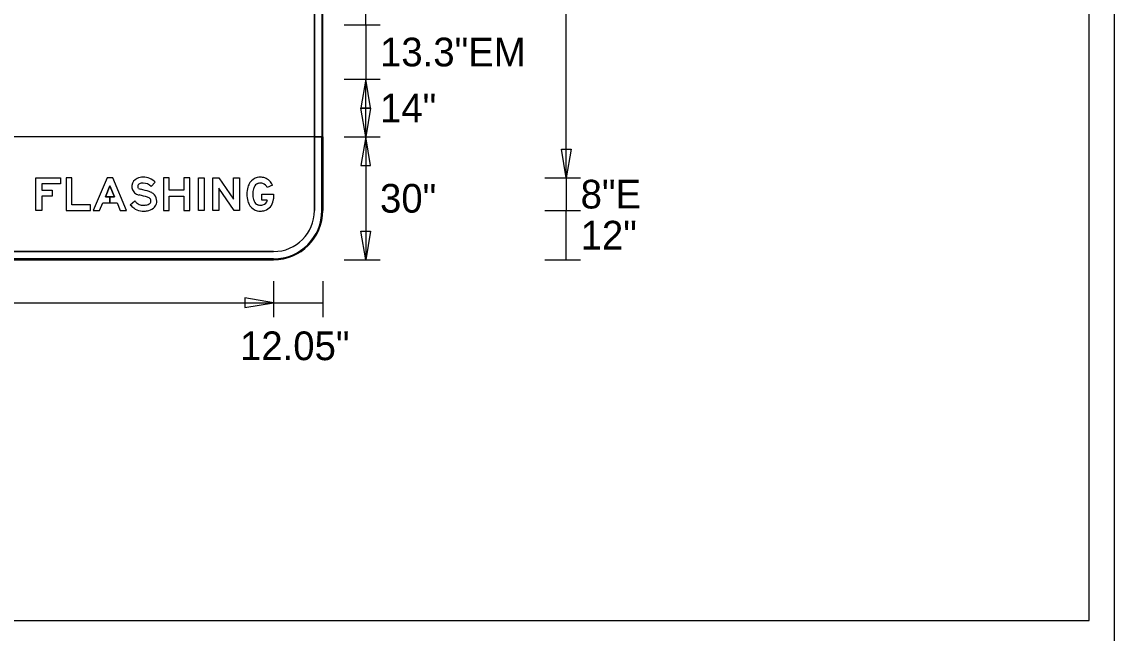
# Model space of a CAD drawing. Extents: x 17890484 to 17890754, y 17897495 to 17897992.
# Drawn here: x 17890542.41 to 17890564.64, y 17897525.26 to 17897537.69 of the extents above; entities that cross this region are included whole.
import ezdxf

# ---------------------------------------------------------------- set-up
doc = ezdxf.new("R2010")
doc.units = 0
for name, color, linetype in [('GSBWFill', 7, 'Continuous'), ('GSColorFill', 7, 'Continuous'), ('GSDims', 7, 'Continuous'), ('GSOutline', 7, 'Continuous'), ('SheetLinesMisc2_dp', 7, 'Continuous')]:
    doc.layers.add(name, color=color, linetype=linetype)

msp = doc.modelspace()

# ---------------------------------------------------------------- linework, layer by layer
at = {"layer": 'GSBWFill'}
for p, q in [((17890548.365, 17897541.854), (17890548.365, 17897533.854)), ((17890548.531, 17897533.854), (17890548.531, 17897541.854)), ((17890548.531, 17897535.354), (17890528.531, 17897535.354)), ((17890548.365, 17897535.187), (17890548.365, 17897535.354)), ((17890548.365, 17897535.354), (17890548.531, 17897535.354)), ((17890548.531, 17897535.354), (17890548.531, 17897533.854)), ((17890548.531, 17897533.854), (17890548.531, 17897535.354)), ((17890548.365, 17897533.854), (17890548.365, 17897535.187)), ((17890529.531, 17897533.021), (17890547.531, 17897533.021)), ((17890547.531, 17897532.854), (17890529.531, 17897532.854)), ((17890529.531, 17897532.854), (17890547.531, 17897532.854)), ((17890547.531, 17897533.021), (17890529.533, 17897533.021)), ((17890529.533, 17897532.854), (17890547.531, 17897532.854))]:
    msp.add_line(p, q, dxfattribs=at)
for points in [[(17890542.815, 17897534.147), (17890542.815, 17897533.854), (17890542.695, 17897533.854), (17890542.695, 17897534.521), (17890543.195, 17897534.521), (17890543.195, 17897534.401), (17890542.815, 17897534.401), (17890542.815, 17897534.267), (17890543.025, 17897534.267), (17890543.025, 17897534.147)], [(17890543.808, 17897533.854), (17890543.808, 17897533.971), (17890543.428, 17897533.971), (17890543.428, 17897534.521), (17890543.308, 17897534.521), (17890543.308, 17897533.854)], [(17890544.295, 17897534.131), (17890544.201, 17897534.131), (17890544.201, 17897534.011), (17890544.345, 17897534.011), (17890544.411, 17897533.854), (17890544.541, 17897533.854), (17890544.261, 17897534.521), (17890544.141, 17897534.521), (17890543.861, 17897533.854), (17890543.991, 17897533.854), (17890544.057, 17897534.011), (17890544.201, 17897534.011), (17890544.201, 17897534.131), (17890544.108, 17897534.131), (17890544.201, 17897534.354)], [(17890545.708, 17897534.267), (17890545.408, 17897534.267), (17890545.408, 17897534.521), (17890545.288, 17897534.521), (17890545.288, 17897533.854), (17890545.408, 17897533.854), (17890545.408, 17897534.147), (17890545.708, 17897534.147), (17890545.708, 17897533.854), (17890545.828, 17897533.854), (17890545.828, 17897534.521), (17890545.708, 17897534.521)], [(17890546.001, 17897533.854), (17890546.001, 17897534.521), (17890546.121, 17897534.521), (17890546.121, 17897533.854)], [(17890546.835, 17897534.521), (17890546.835, 17897533.854), (17890546.731, 17897533.854), (17890546.415, 17897534.311), (17890546.415, 17897533.854), (17890546.295, 17897533.854), (17890546.295, 17897534.521), (17890546.415, 17897534.521), (17890546.715, 17897534.089), (17890546.715, 17897534.521)]]:
    msp.add_lwpolyline(points, close=True, dxfattribs=at)
for points in [[(17890545.124, 17897534.429), (17890545.038, 17897534.345)], [(17890547.51, 17897534.37), (17890547.399, 17897534.325)], [(17890547.404, 17897534.067), (17890547.294, 17897534.067), (17890547.294, 17897534.187), (17890547.528, 17897534.187), (17890547.528, 17897534.091)], [(17890544.615, 17897533.972), (17890544.705, 17897534.051)]]:
    msp.add_lwpolyline(points, dxfattribs=at)
for centre, radius, start, end in [((17890544.837, 17897534.345), 0.191, 174.1421, 201.2247), ((17890544.821, 17897534.346), 0.174, 113.3248, 174.1421), ((17890544.878, 17897534.214), 0.318, 90, 113.3248), ((17890544.821, 17897534.346), 0.0543, 113.3248, 174.1421), ((17890544.878, 17897534.214), 0.198, 90, 113.3248), ((17890544.878, 17897534.187), 0.345, 44.4342, 90), ((17890544.878, 17897534.187), 0.225, 44.4342, 90), ((17890547.342, 17897534.232), 0.348, 146.7742, 163.4624), ((17890547.252, 17897534.291), 0.24, 103.1315, 146.7742), ((17890547.342, 17897534.232), 0.228, 146.7742, 163.4624), ((17890547.252, 17897534.291), 0.12, 103.1315, 146.7742), ((17890547.263, 17897534.243), 0.289, 90, 103.1315), ((17890547.263, 17897534.243), 0.169, 90, 103.1315), ((17890547.263, 17897534.252), 0.28, 71.2015, 90), ((17890547.263, 17897534.252), 0.16, 71.2015, 90), ((17890547.27, 17897534.272), 0.139, 22.0367, 71.2015), ((17890547.27, 17897534.272), 0.259, 22.0367, 71.2015), ((17890544.798, 17897534.33), 0.149, 201.2247, 240.1812), ((17890544.867, 17897534.45), 0.288, 240.1812, 256.1067), ((17890544.837, 17897534.345), 0.0706, 174.1421, 201.2247), ((17890544.798, 17897534.33), 0.029, 201.2247, 240.1812), ((17890544.867, 17897534.45), 0.168, 240.1812, 256.1067), ((17890544.05, 17897531.146), 3.116, 72.8961, 76.1067), ((17890544.05, 17897531.146), 3.236, 72.8961, 76.1067), ((17890544.907, 17897533.933), 0.32, 63.0108, 72.8961), ((17890544.972, 17897534.059), 0.178, 39.5561, 63.0108), ((17890544.955, 17897534.046), 0.199, 0, 39.5561), ((17890547.493, 17897534.187), 0.505, 163.4624, 180), ((17890547.493, 17897534.187), 0.505, 180, 196.5376), ((17890547.493, 17897534.187), 0.385, 163.4624, 180), ((17890547.493, 17897534.187), 0.385, 180, 196.5376), ((17890544.966, 17897534.276), 0.464, 220.8202, 232.6492), ((17890544.966, 17897534.276), 0.344, 220.8202, 232.6492), ((17890544.869, 17897534.149), 0.185, 232.6492, 260.7349), ((17890544.89, 17897534.273), 0.31, 260.7349, 270), ((17890544.89, 17897534.208), 0.245, 270, 281.6446), ((17890544.899, 17897534.159), 0.196, 281.6446, 306.0677), ((17890544.907, 17897533.933), 0.2, 63.0108, 72.8961), ((17890544.972, 17897534.059), 0.0579, 39.5561, 63.0108), ((17890544.988, 17897534.037), 0.045, 306.0677, 343.4972), ((17890544.955, 17897534.046), 0.0794, 0, 39.5561), ((17890544.96, 17897534.046), 0.0746, 343.4972, 0), ((17890544.988, 17897534.037), 0.165, 306.0677, 343.4972), ((17890544.96, 17897534.046), 0.195, 343.4972, 0), ((17890547.342, 17897534.143), 0.348, 196.5376, 213.2258), ((17890547.252, 17897534.084), 0.24, 213.2258, 256.8685), ((17890547.342, 17897534.143), 0.228, 196.5376, 213.2258), ((17890547.252, 17897534.084), 0.12, 213.2258, 256.8685), ((17890547.263, 17897534.132), 0.169, 256.8685, 270), ((17890547.263, 17897534.122), 0.16, 270, 288.7985), ((17890547.27, 17897534.102), 0.139, 288.7985, 345.418), ((17890547.27, 17897534.102), 0.259, 288.7985, 349.6765), ((17890547.33, 17897534.091), 0.198, 349.6765, 0), ((17890544.869, 17897534.149), 0.305, 232.6492, 260.7349), ((17890544.89, 17897534.273), 0.43, 260.7349, 270), ((17890544.89, 17897534.208), 0.365, 270, 281.6446), ((17890544.899, 17897534.159), 0.316, 281.6446, 306.0677), ((17890547.263, 17897534.132), 0.289, 256.8685, 270), ((17890547.263, 17897534.122), 0.28, 270, 288.7985), ((17890547.531, 17897533.854), 1, 270, 0), ((17890547.531, 17897533.854), 0.833, 270, 0), ((17890547.531, 17897533.854), 1, 270, 0), ((17890547.531, 17897533.854), 0.833, 270, 0), ((17890547.531, 17897533.854), 1, 270, 0)]:
    msp.add_arc(centre, radius, start, end, dxfattribs=at)
at = {"layer": 'GSColorFill'}
for p, q in [((17890548.365, 17897541.854), (17890548.365, 17897533.854)), ((17890548.515, 17897541.854), (17890548.515, 17897533.854)), ((17890548.531, 17897533.854), (17890548.531, 17897541.854)), ((17890548.531, 17897533.854), (17890548.531, 17897541.854)), ((17890548.531, 17897533.854), (17890548.531, 17897541.854)), ((17890548.531, 17897535.354), (17890528.531, 17897535.354)), ((17890548.365, 17897535.187), (17890548.365, 17897535.354)), ((17890548.365, 17897535.354), (17890548.531, 17897535.354)), ((17890548.515, 17897535.337), (17890548.515, 17897535.354)), ((17890548.515, 17897535.354), (17890548.531, 17897535.354)), ((17890548.515, 17897533.854), (17890548.515, 17897535.337)), ((17890548.531, 17897533.854), (17890548.531, 17897535.354)), ((17890548.531, 17897535.354), (17890548.531, 17897533.854)), ((17890548.531, 17897535.354), (17890548.531, 17897533.854)), ((17890548.365, 17897533.854), (17890548.365, 17897535.187)), ((17890529.531, 17897533.021), (17890547.531, 17897533.021)), ((17890547.531, 17897532.871), (17890529.531, 17897532.871)), ((17890529.531, 17897532.871), (17890547.531, 17897532.871)), ((17890529.531, 17897532.854), (17890547.531, 17897532.854)), ((17890529.531, 17897532.854), (17890547.531, 17897532.854)), ((17890529.531, 17897532.854), (17890547.531, 17897532.854)), ((17890547.531, 17897532.854), (17890529.531, 17897532.854)), ((17890547.531, 17897532.854), (17890529.531, 17897532.854)), ((17890547.531, 17897533.021), (17890529.533, 17897533.021)), ((17890529.533, 17897532.854), (17890547.531, 17897532.854))]:
    msp.add_line(p, q, dxfattribs=at)
for points in [[(17890542.815, 17897534.147), (17890542.815, 17897533.854), (17890542.695, 17897533.854), (17890542.695, 17897534.521), (17890543.195, 17897534.521), (17890543.195, 17897534.401), (17890542.815, 17897534.401), (17890542.815, 17897534.267), (17890543.025, 17897534.267), (17890543.025, 17897534.147)], [(17890543.808, 17897533.854), (17890543.808, 17897533.971), (17890543.428, 17897533.971), (17890543.428, 17897534.521), (17890543.308, 17897534.521), (17890543.308, 17897533.854)], [(17890544.295, 17897534.131), (17890544.201, 17897534.131), (17890544.201, 17897534.011), (17890544.345, 17897534.011), (17890544.411, 17897533.854), (17890544.541, 17897533.854), (17890544.261, 17897534.521), (17890544.141, 17897534.521), (17890543.861, 17897533.854), (17890543.991, 17897533.854), (17890544.057, 17897534.011), (17890544.201, 17897534.011), (17890544.201, 17897534.131), (17890544.108, 17897534.131), (17890544.201, 17897534.354)], [(17890545.708, 17897534.267), (17890545.408, 17897534.267), (17890545.408, 17897534.521), (17890545.288, 17897534.521), (17890545.288, 17897533.854), (17890545.408, 17897533.854), (17890545.408, 17897534.147), (17890545.708, 17897534.147), (17890545.708, 17897533.854), (17890545.828, 17897533.854), (17890545.828, 17897534.521), (17890545.708, 17897534.521)], [(17890546.001, 17897533.854), (17890546.001, 17897534.521), (17890546.121, 17897534.521), (17890546.121, 17897533.854)], [(17890546.835, 17897534.521), (17890546.835, 17897533.854), (17890546.731, 17897533.854), (17890546.415, 17897534.311), (17890546.415, 17897533.854), (17890546.295, 17897533.854), (17890546.295, 17897534.521), (17890546.415, 17897534.521), (17890546.715, 17897534.089), (17890546.715, 17897534.521)]]:
    msp.add_lwpolyline(points, close=True, dxfattribs=at)
for points in [[(17890545.124, 17897534.429), (17890545.038, 17897534.345)], [(17890547.51, 17897534.37), (17890547.399, 17897534.325)], [(17890547.404, 17897534.067), (17890547.294, 17897534.067), (17890547.294, 17897534.187), (17890547.528, 17897534.187), (17890547.528, 17897534.091)], [(17890544.615, 17897533.972), (17890544.705, 17897534.051)]]:
    msp.add_lwpolyline(points, dxfattribs=at)
for centre, radius, start, end in [((17890544.837, 17897534.345), 0.191, 174.1421, 201.2247), ((17890544.821, 17897534.346), 0.174, 113.3248, 174.1421), ((17890544.878, 17897534.214), 0.318, 90, 113.3248), ((17890544.821, 17897534.346), 0.0543, 113.3248, 174.1421), ((17890544.878, 17897534.214), 0.198, 90, 113.3248), ((17890544.878, 17897534.187), 0.345, 44.4342, 90), ((17890544.878, 17897534.187), 0.225, 44.4342, 90), ((17890547.342, 17897534.232), 0.348, 146.7742, 163.4624), ((17890547.252, 17897534.291), 0.24, 103.1315, 146.7742), ((17890547.342, 17897534.232), 0.228, 146.7742, 163.4624), ((17890547.252, 17897534.291), 0.12, 103.1315, 146.7742), ((17890547.263, 17897534.243), 0.289, 90, 103.1315), ((17890547.263, 17897534.243), 0.169, 90, 103.1315), ((17890547.263, 17897534.252), 0.28, 71.2015, 90), ((17890547.263, 17897534.252), 0.16, 71.2015, 90), ((17890547.27, 17897534.272), 0.139, 22.0367, 71.2015), ((17890547.27, 17897534.272), 0.259, 22.0367, 71.2015), ((17890544.798, 17897534.33), 0.149, 201.2247, 240.1812), ((17890544.867, 17897534.45), 0.288, 240.1812, 256.1067), ((17890544.837, 17897534.345), 0.0706, 174.1421, 201.2247), ((17890544.798, 17897534.33), 0.029, 201.2247, 240.1812), ((17890544.867, 17897534.45), 0.168, 240.1812, 256.1067), ((17890544.05, 17897531.146), 3.116, 72.8961, 76.1067), ((17890544.05, 17897531.146), 3.236, 72.8961, 76.1067), ((17890544.907, 17897533.933), 0.32, 63.0108, 72.8961), ((17890544.972, 17897534.059), 0.178, 39.5561, 63.0108), ((17890544.955, 17897534.046), 0.199, 0, 39.5561), ((17890547.493, 17897534.187), 0.505, 163.4624, 180), ((17890547.493, 17897534.187), 0.505, 180, 196.5376), ((17890547.493, 17897534.187), 0.385, 163.4624, 180), ((17890547.493, 17897534.187), 0.385, 180, 196.5376), ((17890544.966, 17897534.276), 0.464, 220.8202, 232.6492), ((17890544.966, 17897534.276), 0.344, 220.8202, 232.6492), ((17890544.869, 17897534.149), 0.185, 232.6492, 260.7349), ((17890544.89, 17897534.273), 0.31, 260.7349, 270), ((17890544.89, 17897534.208), 0.245, 270, 281.6446), ((17890544.899, 17897534.159), 0.196, 281.6446, 306.0677), ((17890544.907, 17897533.933), 0.2, 63.0108, 72.8961), ((17890544.972, 17897534.059), 0.0579, 39.5561, 63.0108), ((17890544.988, 17897534.037), 0.045, 306.0677, 343.4972), ((17890544.955, 17897534.046), 0.0794, 0, 39.5561), ((17890544.96, 17897534.046), 0.0746, 343.4972, 0), ((17890544.988, 17897534.037), 0.165, 306.0677, 343.4972), ((17890544.96, 17897534.046), 0.195, 343.4972, 0), ((17890547.342, 17897534.143), 0.348, 196.5376, 213.2258), ((17890547.252, 17897534.084), 0.24, 213.2258, 256.8685), ((17890547.342, 17897534.143), 0.228, 196.5376, 213.2258), ((17890547.252, 17897534.084), 0.12, 213.2258, 256.8685), ((17890547.263, 17897534.132), 0.169, 256.8685, 270), ((17890547.263, 17897534.122), 0.16, 270, 288.7985), ((17890547.27, 17897534.102), 0.139, 288.7985, 345.418), ((17890547.27, 17897534.102), 0.259, 288.7985, 349.6765), ((17890547.33, 17897534.091), 0.198, 349.6765, 0), ((17890544.869, 17897534.149), 0.305, 232.6492, 260.7349), ((17890544.89, 17897534.273), 0.43, 260.7349, 270), ((17890544.89, 17897534.208), 0.365, 270, 281.6446), ((17890544.899, 17897534.159), 0.316, 281.6446, 306.0677), ((17890547.263, 17897534.132), 0.289, 256.8685, 270), ((17890547.263, 17897534.122), 0.28, 270, 288.7985), ((17890547.531, 17897533.854), 1, 270, 0), ((17890547.531, 17897533.854), 1, 270, 0), ((17890547.531, 17897533.854), 0.833, 270, 0), ((17890547.531, 17897533.854), 1, 270, 0), ((17890547.531, 17897533.854), 0.983, 270, 0), ((17890547.531, 17897533.854), 1, 270, 0), ((17890547.531, 17897533.854), 1, 270, 0), ((17890547.531, 17897533.854), 0.833, 270, 0), ((17890547.531, 17897533.854), 1, 270, 0), ((17890547.531, 17897533.854), 0.983, 270, 0)]:
    msp.add_arc(centre, radius, start, end, dxfattribs=at)
at = {"layer": 'GSDims'}
for p, q in [((17890553.49, 17897534.521), (17890553.49, 17897542.854)), ((17890549.406, 17897537.633), (17890549.406, 17897538.467)), ((17890548.969, 17897537.633), (17890549.698, 17897537.633)), ((17890548.969, 17897537.633), (17890549.698, 17897537.633)), ((17890549.406, 17897537.633), (17890549.406, 17897536.525)), ((17890548.969, 17897536.525), (17890549.698, 17897536.525)), ((17890548.969, 17897536.525), (17890549.698, 17897536.525)), ((17890549.406, 17897535.354), (17890549.406, 17897536.525)), ((17890548.969, 17897535.354), (17890549.698, 17897535.354)), ((17890548.969, 17897535.354), (17890549.698, 17897535.354)), ((17890549.406, 17897535.354), (17890549.406, 17897532.854)), ((17890553.052, 17897534.521), (17890553.781, 17897534.521)), ((17890553.052, 17897534.521), (17890553.781, 17897534.521)), ((17890553.49, 17897534.521), (17890553.49, 17897533.854)), ((17890553.052, 17897533.854), (17890553.781, 17897533.854)), ((17890553.052, 17897533.854), (17890553.781, 17897533.854)), ((17890553.49, 17897532.854), (17890553.49, 17897533.854)), ((17890548.969, 17897532.854), (17890549.698, 17897532.854)), ((17890553.052, 17897532.854), (17890553.781, 17897532.854)), ((17890547.528, 17897532.417), (17890547.528, 17897531.687)), ((17890547.528, 17897532.417), (17890547.528, 17897531.687)), ((17890548.531, 17897532.417), (17890548.531, 17897531.687)), ((17890529.535, 17897531.979), (17890547.528, 17897531.979)), ((17890547.528, 17897531.979), (17890548.531, 17897531.979))]:
    msp.add_line(p, q, dxfattribs=at)
for points in [[(17890549.406, 17897536.525), (17890549.309, 17897535.942), (17890549.503, 17897535.942)], [(17890549.406, 17897535.354), (17890549.309, 17897535.937), (17890549.503, 17897535.937)], [(17890549.406, 17897535.354), (17890549.309, 17897534.771), (17890549.503, 17897534.771)], [(17890553.49, 17897534.521), (17890553.392, 17897535.104), (17890553.587, 17897535.104)], [(17890549.406, 17897532.854), (17890549.309, 17897533.437), (17890549.503, 17897533.437)], [(17890547.528, 17897531.979), (17890546.945, 17897532.076), (17890546.945, 17897531.882)]]:
    msp.add_lwpolyline(points, close=True, dxfattribs=at)
at = {"layer": 'GSOutline'}
for p, q in [((17890548.365, 17897533.854), (17890548.365, 17897541.854)), ((17890548.531, 17897533.854), (17890548.531, 17897541.854)), ((17890548.531, 17897535.354), (17890528.531, 17897535.354)), ((17890548.365, 17897535.187), (17890548.365, 17897535.354)), ((17890548.365, 17897535.354), (17890548.531, 17897535.354)), ((17890548.531, 17897535.354), (17890548.531, 17897533.854)), ((17890548.531, 17897533.854), (17890548.531, 17897535.354)), ((17890548.365, 17897533.854), (17890548.365, 17897535.187)), ((17890529.531, 17897533.021), (17890547.531, 17897533.021)), ((17890529.531, 17897533.021), (17890547.531, 17897533.021)), ((17890529.531, 17897532.854), (17890547.531, 17897532.854)), ((17890547.531, 17897532.854), (17890529.531, 17897532.854)), ((17890529.531, 17897532.854), (17890547.531, 17897532.854))]:
    msp.add_line(p, q, dxfattribs=at)
for points in [[(17890542.815, 17897534.147), (17890542.815, 17897533.854), (17890542.695, 17897533.854), (17890542.695, 17897534.521), (17890543.195, 17897534.521), (17890543.195, 17897534.401), (17890542.815, 17897534.401), (17890542.815, 17897534.267), (17890543.025, 17897534.267), (17890543.025, 17897534.147)], [(17890543.808, 17897533.854), (17890543.808, 17897533.971), (17890543.428, 17897533.971), (17890543.428, 17897534.521), (17890543.308, 17897534.521), (17890543.308, 17897533.854)], [(17890544.057, 17897534.011), (17890544.345, 17897534.011), (17890544.411, 17897533.854), (17890544.541, 17897533.854), (17890544.261, 17897534.521), (17890544.141, 17897534.521), (17890543.861, 17897533.854), (17890543.991, 17897533.854)], [(17890545.708, 17897534.267), (17890545.408, 17897534.267), (17890545.408, 17897534.521), (17890545.288, 17897534.521), (17890545.288, 17897533.854), (17890545.408, 17897533.854), (17890545.408, 17897534.147), (17890545.708, 17897534.147), (17890545.708, 17897533.854), (17890545.828, 17897533.854), (17890545.828, 17897534.521), (17890545.708, 17897534.521)], [(17890546.001, 17897533.854), (17890546.001, 17897534.521), (17890546.121, 17897534.521), (17890546.121, 17897533.854)], [(17890546.835, 17897534.521), (17890546.835, 17897533.854), (17890546.731, 17897533.854), (17890546.415, 17897534.311), (17890546.415, 17897533.854), (17890546.295, 17897533.854), (17890546.295, 17897534.521), (17890546.415, 17897534.521), (17890546.715, 17897534.089), (17890546.715, 17897534.521)], [(17890544.295, 17897534.131), (17890544.201, 17897534.354), (17890544.108, 17897534.131)]]:
    msp.add_lwpolyline(points, close=True, dxfattribs=at)
for points in [[(17890545.124, 17897534.429), (17890545.038, 17897534.345)], [(17890547.51, 17897534.37), (17890547.399, 17897534.325)], [(17890547.404, 17897534.067), (17890547.294, 17897534.067), (17890547.294, 17897534.187), (17890547.528, 17897534.187), (17890547.528, 17897534.091)], [(17890544.615, 17897533.972), (17890544.705, 17897534.051)]]:
    msp.add_lwpolyline(points, dxfattribs=at)
for centre, radius, start, end in [((17890544.837, 17897534.345), 0.191, 174.1421, 201.2247), ((17890544.821, 17897534.346), 0.174, 113.3248, 174.1421), ((17890544.878, 17897534.214), 0.318, 90, 113.3248), ((17890544.821, 17897534.346), 0.0543, 113.3248, 174.1421), ((17890544.878, 17897534.214), 0.198, 90, 113.3248), ((17890544.878, 17897534.187), 0.345, 44.4342, 90), ((17890544.878, 17897534.187), 0.225, 44.4342, 90), ((17890547.342, 17897534.232), 0.348, 146.7742, 163.4624), ((17890547.252, 17897534.291), 0.24, 103.1315, 146.7742), ((17890547.342, 17897534.232), 0.228, 146.7742, 163.4624), ((17890547.252, 17897534.291), 0.12, 103.1315, 146.7742), ((17890547.263, 17897534.243), 0.289, 90, 103.1315), ((17890547.263, 17897534.243), 0.169, 90, 103.1315), ((17890547.263, 17897534.252), 0.28, 71.2015, 90), ((17890547.263, 17897534.252), 0.16, 71.2015, 90), ((17890547.27, 17897534.272), 0.139, 22.0367, 71.2015), ((17890547.27, 17897534.272), 0.259, 22.0367, 71.2015), ((17890544.798, 17897534.33), 0.149, 201.2247, 240.1812), ((17890544.867, 17897534.45), 0.288, 240.1812, 256.1067), ((17890544.837, 17897534.345), 0.0706, 174.1421, 201.2247), ((17890544.798, 17897534.33), 0.029, 201.2247, 240.1812), ((17890544.867, 17897534.45), 0.168, 240.1812, 256.1067), ((17890544.05, 17897531.146), 3.116, 72.8961, 76.1067), ((17890544.05, 17897531.146), 3.236, 72.8961, 76.1067), ((17890544.907, 17897533.933), 0.32, 63.0108, 72.8961), ((17890544.972, 17897534.059), 0.178, 39.5561, 63.0108), ((17890544.955, 17897534.046), 0.199, 0, 39.5561), ((17890547.493, 17897534.187), 0.505, 163.4624, 180), ((17890547.493, 17897534.187), 0.505, 180, 196.5376), ((17890547.493, 17897534.187), 0.385, 163.4624, 180), ((17890547.493, 17897534.187), 0.385, 180, 196.5376), ((17890544.966, 17897534.276), 0.464, 220.8202, 232.6492), ((17890544.966, 17897534.276), 0.344, 220.8202, 232.6492), ((17890544.869, 17897534.149), 0.185, 232.6492, 260.7349), ((17890544.89, 17897534.273), 0.31, 260.7349, 270), ((17890544.89, 17897534.208), 0.245, 270, 281.6446), ((17890544.899, 17897534.159), 0.196, 281.6446, 306.0677), ((17890544.907, 17897533.933), 0.2, 63.0108, 72.8961), ((17890544.972, 17897534.059), 0.0579, 39.5561, 63.0108), ((17890544.988, 17897534.037), 0.045, 306.0677, 343.4972), ((17890544.955, 17897534.046), 0.0794, 0, 39.5561), ((17890544.96, 17897534.046), 0.0746, 343.4972, 0), ((17890544.988, 17897534.037), 0.165, 306.0677, 343.4972), ((17890544.96, 17897534.046), 0.195, 343.4972, 0), ((17890547.342, 17897534.143), 0.348, 196.5376, 213.2258), ((17890547.252, 17897534.084), 0.24, 213.2258, 256.8685), ((17890547.342, 17897534.143), 0.228, 196.5376, 213.2258), ((17890547.252, 17897534.084), 0.12, 213.2258, 256.8685), ((17890547.263, 17897534.132), 0.169, 256.8685, 270), ((17890547.263, 17897534.122), 0.16, 270, 288.7985), ((17890547.27, 17897534.102), 0.139, 288.7985, 345.418), ((17890547.27, 17897534.102), 0.259, 288.7985, 349.6765), ((17890547.33, 17897534.091), 0.198, 349.6765, 0), ((17890544.869, 17897534.149), 0.305, 232.6492, 260.7349), ((17890544.89, 17897534.273), 0.43, 260.7349, 270), ((17890544.89, 17897534.208), 0.365, 270, 281.6446), ((17890544.899, 17897534.159), 0.316, 281.6446, 306.0677), ((17890547.263, 17897534.132), 0.289, 256.8685, 270), ((17890547.263, 17897534.122), 0.28, 270, 288.7985), ((17890547.531, 17897533.854), 1, 270, 0), ((17890547.531, 17897533.854), 0.833, 270, 0), ((17890547.531, 17897533.854), 1, 270, 0), ((17890547.531, 17897533.854), 0.833, 270, 0), ((17890547.531, 17897533.854), 1, 270, 0)]:
    msp.add_arc(centre, radius, start, end, dxfattribs=at)
at = {"layer": 'SheetLinesMisc2_dp'}
for p, q in [((17890564.641, 17897597.808), (17890564.641, 17897504.15)), ((17890564.129, 17897525.552), (17890564.129, 17897550.443)), ((17890512.958, 17897525.517), (17890564.13, 17897525.517)), ((17890564.129, 17897525.518), (17890564.129, 17897525.552))]:
    msp.add_line(p, q, dxfattribs=at)

# ---------------------------------------------------------------- texts
at = {"layer": 'GSDims'}
for s, p in [('13.3"EM', (17890549.698, 17897536.787)), ('14"', (17890549.698, 17897535.648)), ('30"', (17890549.698, 17897533.812)), ('8"E', (17890553.781, 17897533.896)), ('12"', (17890553.781, 17897533.062)), ('12.05"', (17890546.848, 17897530.812))]:
    msp.add_text(s, height=0.5833, dxfattribs=at).set_placement(p)

doc.saveas('drawing.dxf')
